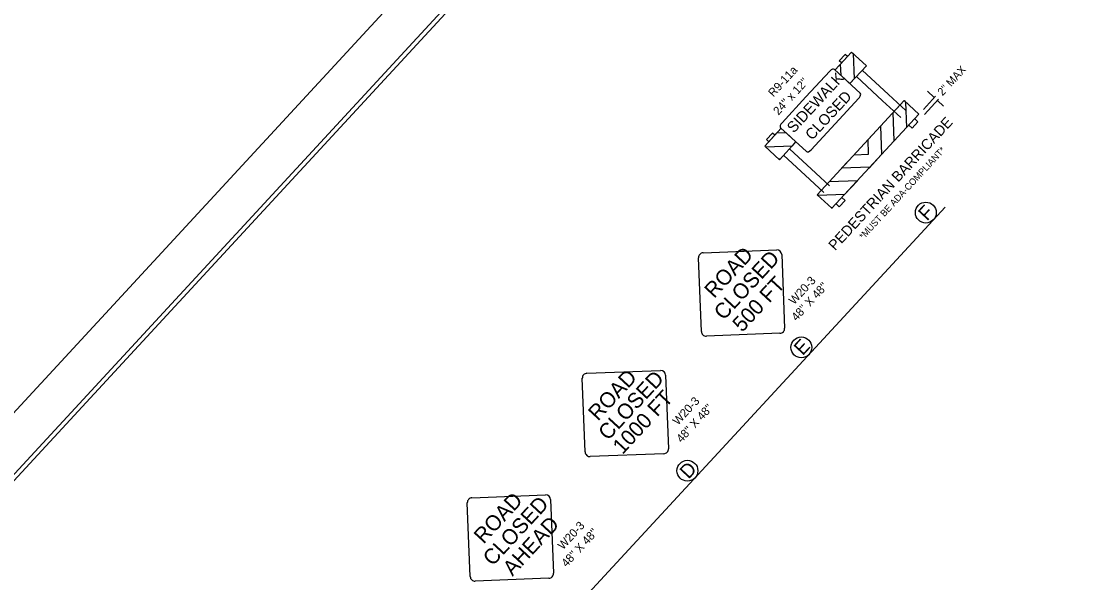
# Model space of a CAD drawing. Extents: x 1767460 to 1770129, y 996106 to 1001438.
# Drawn here: x 1768524 to 1769280, y 1000630 to 1001034 of the extents above; entities that cross this region are included whole.
import ezdxf

# ---------------------------------------------------------------- set-up
doc = ezdxf.new("R2010")
doc.units = 0
for name, color, linetype in [('_CIVIL_CONSTRUCTION', 7, 'Continuous'), ('E_NCDOT_Terrain_Model_Contour_Minor', 7, 'Continuous'), ('E_NCDOT_Terrain_Model_Points_Low', 7, 'Continuous'), ('E_NCDOT_Terrain_Model_Triangle_Vertices', 7, 'Continuous'), ('P_NCDOT_Terrain_Flow_Arrows', 7, 'Continuous'), ('P_NCDOT_Terrain_Points_High', 7, 'Continuous'), ('P_NCDOT_Terrain_Points_Low', 7, 'Continuous'), ('P_NCDOT_Terrain_Void', 7, 'Continuous'), ('P_RDY_Slope_Stake_Fill_Limits', 7, 'Continuous'), ('P_RDY_TL_Centerline', 7, 'Continuous'), ('P_RDY_TL_Centerline_Sub', 7, 'Continuous'), ('P_RDY_TL_Pavement_Marking_Yellow', 7, 'Continuous')]:
    doc.layers.add(name, color=color, linetype=linetype)

msp = doc.modelspace()

# ---------------------------------------------------------------- linework, layer by layer
at = {"layer": '_CIVIL_CONSTRUCTION'}
for centre in [(1769175.26, 1000896.67), (1769085.69, 1000799.76), (1769003.71, 1000711.08)]:
    msp.add_circle(centre, 7.5, dxfattribs=at)
at = {"layer": 'E_NCDOT_Terrain_Model_Contour_Minor'}
msp.add_lwpolyline([(1768744.05, 999038.07), (1770128.77, 1000536.12), (1769152.55, 1001438.49), (1767767.83, 999940.44)], close=True, dxfattribs=at)
at = {"layer": 'E_NCDOT_Terrain_Model_Points_Low'}
msp.add_lwpolyline([(1767804.38, 999935.46), (1769171.05, 1001413.98), (1770107.33, 1000548.53), (1768740.66, 999070.01)], close=True, dxfattribs=at)
at = {"layer": 'E_NCDOT_Terrain_Model_Triangle_Vertices'}
msp.add_lwpolyline([(1769163.02, 1001400.87), (1767932.52, 1000069.67), (1768864.37, 999208.32), (1770094.87, 1000539.52)], close=True, dxfattribs=at)
at = {"layer": 'P_NCDOT_Terrain_Flow_Arrows'}
for p, q in [((1769127.07, 1000978.96), (1769109.94, 1000960.43)), ((1769109.94, 1000960.43), (1769092.8, 1000941.89))]:
    msp.add_line(p, q, dxfattribs=at)
for points in [[(1769088.95, 1000979.82), (1769106.09, 1000998.36)], [(1769109.57, 1000999.68), (1769128.11, 1000982.54)], [(1769071.82, 1000961.29), (1769088.95, 1000979.82)], [(1769089.32, 1000940.57), (1769070.78, 1000957.71)]]:
    msp.add_lwpolyline(points, dxfattribs=at)
for centre, major_axis, start_param, end_param in [((1769107.31, 1000997.23), (2.26, 2.45), 0, 1.570796), ((1769125.85, 1000980.09), (-2.26, -2.45), 1.570796, 3.141593), ((1769073.04, 1000960.16), (-2.26, -2.45), 4.712162, 6.283185), ((1769091.58, 1000943.02), (-2.26, -2.45), 0, 1.570796)]:
    msp.add_ellipse(centre, major_axis=major_axis, ratio=0.5, start_param=start_param, end_param=end_param, dxfattribs=at)
at = {"layer": 'P_NCDOT_Terrain_Points_High'}
msp.add_lwpolyline([(1769163.02, 1001400.87), (1767932.52, 1000069.67), (1768864.37, 999208.32), (1769639.43, 1000046.81), (1769513.61, 1000163.11), (1769964.83, 1000651.25), (1769968.19, 1000656.62)], close=True, dxfattribs=at)
at = {"layer": 'P_NCDOT_Terrain_Points_Low'}
for p, q in [((1769121.87, 1001012.12), (1769110, 1000999.28)), ((1769117.25, 1001010.43), (1769113, 1001005.84)), ((1769113.92, 1001003.52), (1769121.87, 1001012.12)), ((1769118.9, 1001008.9), (1769117.21, 1001010.47)), ((1769132.48, 1001002.31), (1769121.87, 1001012.12)), ((1769114.65, 1001004.31), (1769113, 1001005.84)), ((1769114.24, 1000995.36), (1769113.92, 1001003.52)), ((1769120.62, 1000989.47), (1769132.48, 1001002.31)), ((1769144.15, 1000977.05), (1769125.27, 1000994.5)), ((1769148.39, 1000981.64), (1769129.51, 1000999.09)), ((1769160.79, 1000970.18), (1769148.39, 1000981.64)), ((1769173.49, 1000970.91), (1769182.2, 1000980.32)), ((1769176.37, 1000983.9), (1769181.29, 1000979.35)), ((1769159.64, 1000977.21), (1769097.1, 1000909.56)), ((1769157.19, 1000964.99), (1769144.15, 1000977.05)), ((1769151.69, 1000968.61), (1769159.64, 1000977.21)), ((1769170.25, 1000967.4), (1769159.64, 1000977.21)), ((1769174.32, 1000967.2), (1769184.49, 1000978.2)), ((1769183.59, 1000977.23), (1769188.04, 1000973.11)), ((1769107.72, 1000899.75), (1769170.25, 1000967.4)), ((1769152.49, 1000948.19), (1769151.69, 1000968.61)), ((1769169.57, 1000962.06), (1769167.28, 1000964.19)), ((1769071.21, 1000957.31), (1769059.34, 1000944.47)), ((1769133.68, 1000949.13), (1769142.68, 1000958.87)), ((1769142.68, 1000958.87), (1769143.48, 1000938.45)), ((1769161.49, 1000957.93), (1769152.49, 1000948.19)), ((1769165.33, 1000957.47), (1769163.03, 1000959.59)), ((1769169.57, 1000962.06), (1769165.33, 1000957.47)), ((1769067.89, 1000953.71), (1769059.34, 1000944.47)), ((1769064.91, 1000953.81), (1769060.66, 1000949.21)), ((1769062.31, 1000947.68), (1769060.66, 1000949.21)), ((1769066.56, 1000952.28), (1769064.91, 1000953.81)), ((1769074.8, 1000953.99), (1769067.89, 1000953.71)), ((1769134.09, 1000938.7), (1769133.68, 1000949.13)), ((1769059.34, 1000944.47), (1769069.95, 1000934.66)), ((1769069.95, 1000934.66), (1769081.82, 1000947.5)), ((1769096.05, 1000925.02), (1769077.17, 1000942.47)), ((1769070.3, 1000935.04), (1769069.57, 1000935.01)), ((1769069.95, 1000934.66), (1769070.3, 1000935.04)), ((1769091.81, 1000920.42), (1769072.92, 1000937.87)), ((1769114.65, 1000928.55), (1769123.66, 1000938.29)), ((1769123.66, 1000938.29), (1769134.09, 1000938.7)), ((1769143.48, 1000938.45), (1769134.48, 1000928.71)), ((1769135.08, 1000929.35), (1769114.65, 1000928.55)), ((1769101.79, 1000911.2), (1769091.81, 1000920.42)), ((1769105.97, 1000915.85), (1769096.05, 1000925.02)), ((1769105.65, 1000918.81), (1769097.1, 1000909.56)), ((1769126.07, 1000919.61), (1769105.65, 1000918.81)), ((1769117.07, 1000909.87), (1769126.07, 1000919.61)), ((1769097.1, 1000909.56), (1769107.72, 1000899.75)), ((1769117.23, 1000905.44), (1769112.99, 1000900.84)), ((1769117.23, 1000905.44), (1769114.94, 1000907.56)), ((1769108.07, 1000900.13), (1769107.34, 1000900.1)), ((1769107.72, 1000899.75), (1769108.07, 1000900.13)), ((1769112.99, 1000900.84), (1769110.69, 1000902.97))]:
    msp.add_line(p, q, dxfattribs=at)
for points in [[(1769121.87, 1001012.12), (1769123.01, 1001011.07), (1769123.73, 1000992.83)], [(1769123.73, 1000992.83), (1769120.62, 1000989.47), (1769114.24, 1000995.36)], [(1769159.64, 1000977.21), (1769160.77, 1000976.16), (1769161.49, 1000957.93)], [(1769079.31, 1000944.78), (1769081.82, 1000947.5), (1769074.8, 1000953.99)], [(1769059.34, 1000944.47), (1769059.83, 1000944.01), (1769079.31, 1000944.78)], [(1769097.1, 1000909.56), (1769097.6, 1000909.1), (1769117.07, 1000909.87)]]:
    msp.add_lwpolyline(points, dxfattribs=at)
at = {"layer": 'P_NCDOT_Terrain_Void'}
msp.add_line((1768653.55, 1000321.21), (1769189.14, 1000900.63), dxfattribs=at)
at = {"layer": 'P_RDY_TL_Centerline'}
msp.add_line((1768905.28, 1000690.32), (1768907.36, 1000637.36), dxfattribs=at)
for points in [[(1768848.68, 1000691.59), (1768901.64, 1000693.68)], [(1768847.4, 1000635), (1768845.32, 1000687.96)], [(1768904, 1000633.72), (1768851.04, 1000631.64)]]:
    msp.add_lwpolyline(points, dxfattribs=at)
for centre, start, end in [((1768848.82, 1000688.1), 92.2382, 137.24471), ((1768901.78, 1000690.18), 2.25123, 92.25123), ((1768848.82, 1000688.1), 137.24471, 182.25123), ((1768850.9, 1000635.14), 182.25123, 272.25123), ((1768903.86, 1000637.22), 272.25123, 317.25123), ((1768903.86, 1000637.22), 317.25123, 2.25123)]:
    msp.add_arc(centre, 3.5, start, end, dxfattribs=at)
at = {"layer": 'P_RDY_TL_Centerline_Sub'}
for points in [[(1768931.41, 1000781.14), (1768984.37, 1000783.22)], [(1768930.13, 1000724.55), (1768928.05, 1000777.51)], [(1768988.01, 1000779.86), (1768990.09, 1000726.9)], [(1768986.73, 1000723.27), (1768933.77, 1000721.19)]]:
    msp.add_lwpolyline(points, dxfattribs=at)
for centre, start, end in [((1768984.51, 1000779.72), 2.25123, 92.25123), ((1768931.55, 1000777.64), 137.24471, 182.25123), ((1768931.55, 1000777.64), 92.2382, 137.24471), ((1768933.63, 1000724.68), 182.25123, 272.25123), ((1768986.59, 1000726.77), 272.25123, 317.25123), ((1768986.59, 1000726.77), 317.25123, 2.25123)]:
    msp.add_arc(centre, 3.5, start, end, dxfattribs=at)
at = {"layer": 'P_RDY_TL_Pavement_Marking_Yellow'}
msp.add_line((1769071.61, 1000866.51), (1769073.69, 1000813.55), dxfattribs=at)
for points in [[(1769015.01, 1000867.79), (1769067.97, 1000869.87)], [(1769013.74, 1000811.19), (1769011.65, 1000864.15)], [(1769070.33, 1000809.92), (1769017.37, 1000807.83)]]:
    msp.add_lwpolyline(points, dxfattribs=at)
for centre, start, end in [((1769015.15, 1000864.29), 137.24471, 182.25123), ((1769015.15, 1000864.29), 92.2382, 137.24471), ((1769068.11, 1000866.37), 2.25123, 92.25123), ((1769070.19, 1000813.41), 317.25123, 2.25123), ((1769017.23, 1000811.33), 182.25123, 272.25123), ((1769070.19, 1000813.41), 272.25123, 317.25123)]:
    msp.add_arc(centre, 3.5, start, end, dxfattribs=at)

# ---------------------------------------------------------------- texts
at = {"layer": '_CIVIL_CONSTRUCTION'}
for s, p in [('F', (1769176.15, 1000890.26)), ('E', (1769086.66, 1000793.45)), ('D', (1769004.55, 1000704.62))]:
    msp.add_text(s, height=10, rotation=47.25123, dxfattribs=at).set_placement(p)
at = {"layer": 'P_NCDOT_Terrain_Flow_Arrows'}
for s, p in [('SIDEWALK', (1769080.25, 1000953.43)), ('CLOSED', (1769093.44, 1000948.29))]:
    msp.add_text(s, height=7.785, rotation=47.25123, dxfattribs=at).set_placement(p)
at = {"layer": 'P_NCDOT_Terrain_Points_Low'}
for s, height, p in [('2" MAX', 5.715, (1769187.27, 1000980.21)), ('PEDESTRIAN BARRICADE', 7.5076, (1769109.98, 1000868.93)), ('*MUST BE ADA-COMPLIANT*', 4.7627, (1769130.33, 1000877.02))]:
    msp.add_text(s, height=height, rotation=47.25123, dxfattribs=at).set_placement(p)
at = {"layer": 'P_RDY_Slope_Stake_Fill_Limits'}
for s, p in [('R9-11a', (1769065.6, 1000979.43)), ("24'' x 12''", (1769069.23, 1000966.37))]:
    msp.add_text(s, height=6, rotation=47.25123, dxfattribs=at).set_placement(p)
at = {"layer": 'P_RDY_TL_Centerline'}
for s, height, p in [('ROAD', 11, (1768857.02, 1000657.93)), ('CLOSED', 11, (1768863.54, 1000641.98)), ('AHEAD', 11, (1768877.85, 1000634.74)), ('W20-3', 6, (1768914.16, 1000653.86)), ("48'' X 48''", 6, (1768916.78, 1000641.34))]:
    msp.add_text(s, height=height, rotation=47.25123, dxfattribs=at).set_placement(p)
at = {"layer": 'P_RDY_TL_Centerline_Sub'}
for s, height, p in [('ROAD', 11, (1768939.3, 1000746.38)), ('CLOSED', 11, (1768946.55, 1000732.24)), ('1000 FT', 11, (1768956.96, 1000722.27)), ('W20-3', 6, (1768996.89, 1000743.41)), ("48'' X 48''", 6, (1768999.51, 1000730.88))]:
    msp.add_text(s, height=height, rotation=47.25123, dxfattribs=at).set_placement(p)
at = {"layer": 'P_RDY_TL_Pavement_Marking_Yellow'}
for s, height, p in [('ROAD', 11, (1769022.94, 1000834.51)), ('CLOSED', 11, (1769029.77, 1000818.68)), ('500 FT', 11, (1769043.13, 1000810.15)), ('W20-3', 6, (1769080.49, 1000830.06)), ("48'' X 48''", 6, (1769082.26, 1000818.32))]:
    msp.add_text(s, height=height, rotation=47.25123, dxfattribs=at).set_placement(p)

doc.saveas('drawing.dxf')
